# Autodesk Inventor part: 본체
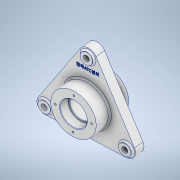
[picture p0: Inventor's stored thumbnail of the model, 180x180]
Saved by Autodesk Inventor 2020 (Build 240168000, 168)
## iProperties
Created: 2023-04
Part Number: 본체
Material: Aluminum 6061
Document SubType Name: Modeling
Designer: home
Density: 2.7 g/cm^3
Appearance: Aluminum - Flat
Mass: 1221.4 g
Surface Area: 646.868 cm^2
Volume: 452.371 cm^3
Author: home
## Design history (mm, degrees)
sketch "Sketch1" dims "d0" = 164
  geometry: L1 (-13.856, 90)-(-84.87, -33); L2 (13.856, 90)-(84.87, -33); L3 (-71.014, -57)-(71.014, -57); A1 r 16 centre (0, 82) between (-13.856, 90) and (13.856, 90); A2 r 16 centre (-71.014, -41) between (-71.014, -57) and (-84.87, -33); A3 r 16 centre (71.014, -41) between (84.87, -33) and (71.014, -57); 2 further points
  constraints: 6 end point, 6 point on circle, 5 tangent, 3 centre point, 2 vertical alignment, 1 coincident, 1 horizontal, 9 other
  dimensions: "d1" = 32 diameter of A1; "d4" = 360 deg dimension on point (0, 0) A1.centre (derived)
extrude "Extrusion1" new body sketch "Sketch1" stored distance "d6" = 18; taper "d7" = 0 deg
sketch "Sketch2"
  geometry: L1 (90, 9)-(-33, 9) reference; L2 (-33, -9)-(90, -9) reference; L3 (0, 32)-(0, -38); L4 (45, 9)-(45, 14); L5 (45, 14)-(40, 14); L6 (40, 14)-(40, 32); L7 (40, 32)-(0, 32); L8 (40, -4.592)-(40, -38); L9 (40, -38)-(0, -38); 4 further points
  constraints: 14 end point, 4 perpendicular, 3 vertical, 2 point on line
  dimensions: "d8" = 90 diameter of L4 L3; "d9" = 80 diameter of L6 L3; "d10" = 80 diameter of L8 L3; "d11" = 5 distance between parallel lines of L1 L5; "d12" = 23 distance between parallel lines of L7 L1; "d13" = 70 distance between parallel lines of L9 L7
revolve "Revolution1" sketch "Sketch2" stored, may be unused: angle "d14" = 90 deg
sketch "Sketch3"
  geometry: C1 r 23.5 at (0, 0); 1 further point
  constraints: 1 centre point, 1 coincident
  dimensions: "d15" = 47 diameter of C1
extrude "Extrusion2" cut sketch "Sketch3" distance "d16" = 17; taper "d17" = 0 deg
sketch "Sketch4"
  geometry: C1 r 23.5 at (0, 0); 1 further point
  constraints: 1 centre point, 1 coincident
  dimensions: "d18" = 47 diameter of C1
extrude "Extrusion3" cut sketch "Sketch4" distance "d19" = 17; taper "d20" = 0 deg
sketch "Sketch5"
  geometry: C1 r 21 at (0, 0); 1 further point
  constraints: 1 centre point, 1 coincident
  dimensions: "d21" = 42 diameter of C1
extrude "Extrusion4" cut sketch "Sketch5" extent not by distance; stored distance "d22" = 17; taper "d23" = 0 deg
sketch "Sketch6"
  geometry: 2 further points
  constraints: 1 vertical alignment
  dimensions: "d24" = 32 distance of point (0, 32) point (0, 0)
hole "Hole1" sketch "Sketch6" at (0, 32) diameter "d25" = 3.242; stored, may be unused: countersink angle "d29" = 90 deg, drill point angle "d31" = 118 deg; dims "d26" = 8, "d27" = 4, "d28" = 2, "d30" = 10
pattern_circular "Circular Pattern1" dims angle "d33" = 360 deg
sketch "Sketch7"
  geometry: 2 further points
  constraints: 1 vertical alignment
  dimensions: "d35" = 32 distance of point (0, 0) point (0, 32)
hole "Hole2" sketch "Sketch7" at (0, 32) diameter "d36" = 3.242; stored, may be unused: countersink angle "d40" = 90 deg, drill point angle "d42" = 118 deg; dims "d37" = 8, "d38" = 4, "d39" = 2, "d41" = 10
pattern_circular "Circular Pattern2" dims angle "d44" = 360 deg
sketch "Sketch8"
  geometry: C1 r 11 at (0, 82); A1 r 16 centre (0, 82) between (13.856, 90) and (-13.856, 90) reference; 1 further point
  constraints: 1 centre point, 1 concentric, 1 vertical alignment
  dimensions: "d46" = 22 diameter of C1
extrude "Extrusion5" join sketch "Sketch8" distance "d48" = 4; taper "d49" = 0 deg
sketch "Sketch9"
  geometry: C1 r 5.5 at (0, 0); C2 r 11 at (0, 0) reference; 2 further points
  constraints: 1 centre point, 1 coincident, 1 concentric
  dimensions: "d50" = 11 diameter of C1
extrude "Extrusion6" cut sketch "Sketch9" extent not by distance; stored distance "d51" = 0; taper "d52" = 0 deg
pattern_circular "Circular Pattern3" dims angle "d54" = 360 deg
fillet "Fillet1" dims "d56" = 3
chamfer "Chamfer1" distance "d57" = 1; stored, may be unused: second distance "d58" = 2, angle "d59" = 45 deg
sketch "Sketch10"
  geometry: L1 (-34.095, 64.049)-(34.095, 64.049); L2 (34.095, 64.049)-(34.095, 57.5); L3 (34.095, 57.5)-(-34.095, 57.5); L4 (-34.095, 57.5)-(-34.095, 64.049); 2 further points
  constraints: 1 midpoint, 1 vertical alignment, 2 other
  dimensions: "d60" = 57.5 distance from line of point (0, 0) L3
emboss "Emboss1" sketch "Sketch10" dims "d8" = 90, "d9" = 80, "d10" = 80, "d11" = 5, "d12" = 23, "d13" = 70, "d61" = 0.5, "d62" = 0
body "Solid1"
